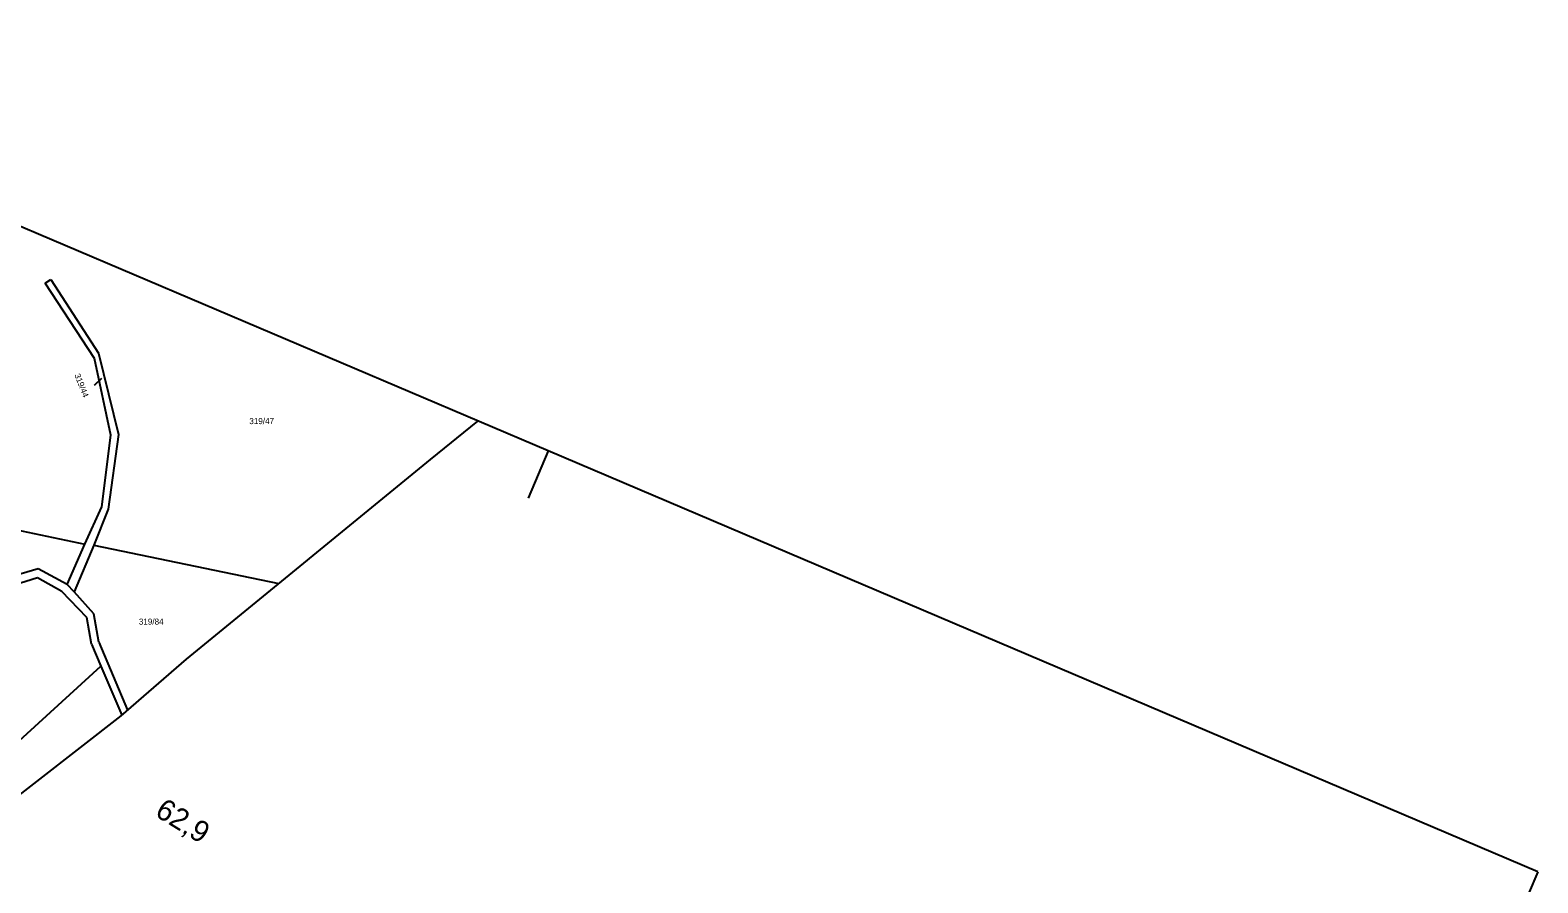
# Model space of a CAD drawing. Extents: x -805826 to -803822, y -1165880 to -1164382.
# Drawn here: x -804669 to -803822, y -1165099 to -1164619 of the extents above; entities that cross this region are included whole.
import ezdxf

# ---------------------------------------------------------------- set-up
doc = ezdxf.new("R2010")
doc.units = 0
for name, color, linetype in [('formát', 7, 'Continuous'), ('kilometráž - 2880', 7, 'Continuous'), ('kn_celek - Cisla parcel pomocna', 7, 'Continuous'), ('kn_celek - Cisla pozemkovych parcel', 7, 'Continuous'), ('kn_celek - Hranice KU 1_2880', 7, 'Continuous'), ('kn_celek - Hranice parcel', 7, 'Continuous')]:
    doc.layers.add(name, color=color, linetype=linetype)

msp = doc.modelspace()

# ---------------------------------------------------------------- linework, layer by layer
at = {"layer": 'formát'}
for p, q in [((-804378.13, -1164855.64), (-804934.65, -1164618.86)), ((-804378.13, -1164855.64), (-804389.4, -1164882.14)), ((-803821.61, -1165092.43), (-804378.13, -1164855.64)), ((-803821.61, -1165092.43), (-804156.49, -1165879.51))]:
    msp.add_line(p, q, dxfattribs=at)
at = {"layer": 'kn_celek - Cisla parcel pomocna'}
msp.add_line((-804629.4, -1164814.81), (-804633.44, -1164818.85), dxfattribs=at)
at = {"layer": 'kn_celek - Hranice KU 1_2880'}
for p, q in [((-804444.28, -1164860.5), (-804417.68, -1164838.82)), ((-804581.63, -1164972.72), (-804444.28, -1164860.5)), ((-804618.36, -1165004.7), (-804581.63, -1164972.72)), ((-804701.79, -1165069.72), (-804618.36, -1165004.7))]:
    msp.add_line(p, q, dxfattribs=at)
at = {"layer": 'kn_celek - Hranice parcel'}
for p, q in [((-804661.02, -1164761.2), (-804657.88, -1164759.13)), ((-804633.27, -1164803.68), (-804661.02, -1164761.2)), ((-804657.88, -1164759.13), (-804631.08, -1164800.66)), ((-804624.18, -1164846.81), (-804633.27, -1164803.68)), ((-804631.08, -1164800.66), (-804619.83, -1164846.46)), ((-804444.28, -1164860.5), (-804417.68, -1164838.82)), ((-804629.21, -1164887.04), (-804624.18, -1164846.81)), ((-804619.83, -1164846.46), (-804625.64, -1164888.46)), ((-804581.63, -1164972.72), (-804444.28, -1164860.5)), ((-804832.6, -1164867.72), (-804638.79, -1164908.07)), ((-804638.79, -1164908.07), (-804629.21, -1164887.04)), ((-804625.64, -1164888.46), (-804633.59, -1164908.58)), ((-804648.71, -1164930.89), (-804638.79, -1164908.07)), ((-804633.59, -1164908.58), (-804644.79, -1164934.97)), ((-804633.59, -1164908.58), (-804529.6, -1164930.21)), ((-804664.89, -1164921.99), (-804705.25, -1164933.71)), ((-804648.71, -1164930.89), (-804664.89, -1164921.99)), ((-804665.39, -1164926.98), (-804704.68, -1164939.45)), ((-804651.63, -1164934.73), (-804665.39, -1164926.98)), ((-804644.79, -1164934.97), (-804648.71, -1164930.89)), ((-804637.52, -1164949.44), (-804651.63, -1164934.73)), ((-804633.63, -1164947.26), (-804644.79, -1164934.97)), ((-804630.91, -1164963.19), (-804633.63, -1164947.26)), ((-804634.96, -1164964.38), (-804637.52, -1164949.44)), ((-804634.96, -1164964.38), (-804629.65, -1164976.8)), ((-804630.91, -1164963.19), (-804614.69, -1165001.51)), ((-804618.36, -1165004.7), (-804581.63, -1164972.72)), ((-804711.07, -1165051.06), (-804629.65, -1164976.8)), ((-804629.65, -1164976.8), (-804617.88, -1165004.32)), ((-804701.79, -1165069.72), (-804618.36, -1165004.7))]:
    msp.add_line(p, q, dxfattribs=at)

# ---------------------------------------------------------------- texts
at = {"layer": 'kilometráž - 2880'}
msp.add_text('62,9', height=12, rotation=328.37907, dxfattribs=at).set_placement((-804599.94, -1165060.6))
at = {"layer": 'kn_celek - Cisla parcel pomocna'}
msp.add_text('319/44', height=3.4, rotation=291.519, dxfattribs=at).set_placement((-804644.66, -1164812.95))
at = {"layer": 'kn_celek - Cisla pozemkovych parcel'}
for s, height, p in [('319/44', 0.005, (-804629.4, -1164814.81)), ('319/47', 3.4, (-804546.23, -1164840.55)), ('319/84', 3.4, (-804608.36, -1164953.38))]:
    msp.add_text(s, height=height, dxfattribs=at).set_placement(p)

doc.saveas('drawing.dxf')
